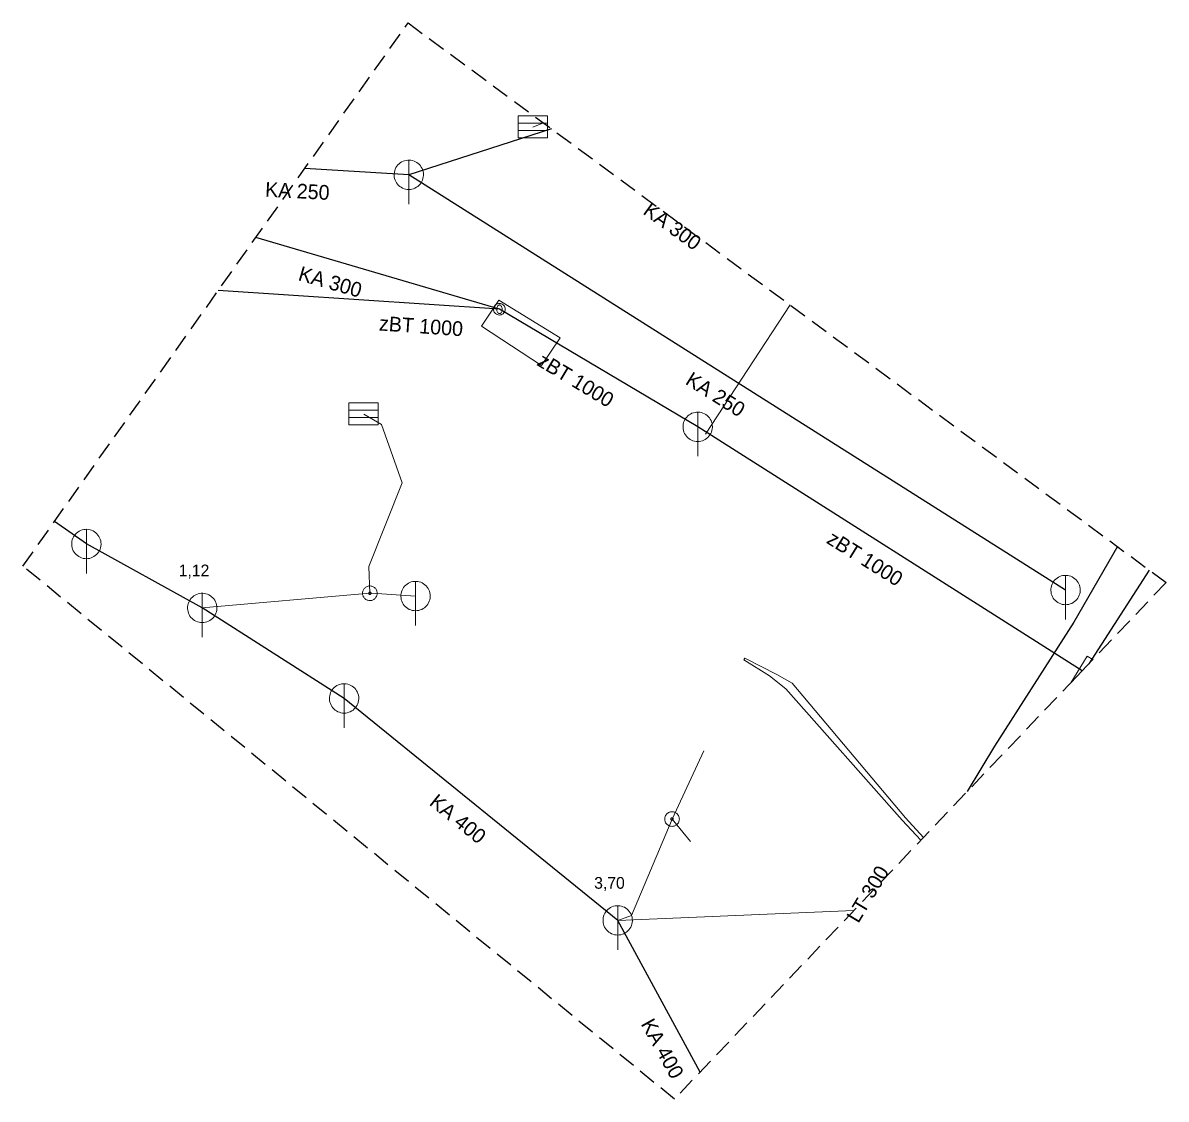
# Model space of a CAD drawing. Extents: x -688182.3 to -688104.4, y -974084.7 to -974011.4.
import ezdxf

# ---------------------------------------------------------------- set-up
doc = ezdxf.new("R2010")
doc.units = 0
doc.header["$LTSCALE"] = 0.4
doc.linetypes.add('MEDIUM_DASHED', pattern=[4.5, 3, -1.5])
for name, color, linetype, lineweight in [('1', 7, 'Continuous', 13), ('11', 7, 'Continuous', 13), ('13', 7, 'Continuous', 13), ('14', 7, 'Continuous', 25), ('17', 7, 'Continuous', 25), ('22', 7, 'Continuous', 13), ('31', 7, 'Continuous', 13)]:
    doc.layers.add(name, color=color, linetype=linetype, lineweight=lineweight)

msp = doc.modelspace()

# ---------------------------------------------------------------- linework, layer by layer
at = {"layer": '1', "linetype": 'MEDIUM_DASHED', "lineweight": 25}
msp.add_lwpolyline([(-688182.317, -974048.412), (-688156.08, -974011.429), (-688104.442, -974049.529), (-688137.937, -974084.698)], close=True, dxfattribs=at)
at = {"layer": '1'}
for points in [[(-688149.886, -974030.3), (-688145.719, -974032.861), (-688146.988, -974034.745), (-688151.07, -974032.079)], [(-688110.944, -974056.356), (-688109.826, -974054.535), (-688109.438, -974054.774)]]:
    msp.add_lwpolyline(points, close=True, dxfattribs=at)
at = {"layer": '11'}
for p, q in [((-688147.579, -974018.52), (-688146.863, -974018.229)), ((-688158.68, -974050.26), (-688170.1, -974051.26)), ((-688135.94, -974060.98), (-688138.1, -974065.629)), ((-688136.85, -974067.16), (-688138.1, -974065.629)), ((-688125.718, -974071.868), (-688141.8, -974072.53))]:
    msp.add_line(p, q, dxfattribs=at)
for points in [[(-688159.1, -974038.059), (-688157.879, -974038.76), (-688156.489, -974042.739), (-688158.76, -974048.43), (-688158.68, -974050.26)], [(-688155.57, -974050.449), (-688157.859, -974050.3), (-688158.68, -974050.26)], [(-688138.1, -974065.629), (-688140.87, -974072.19), (-688141.8, -974072.53)]]:
    msp.add_lwpolyline(points, dxfattribs=at)
at = {"layer": '13'}
msp.add_line((-688130.061, -974030.627), (-688135.823, -974039.428), dxfattribs=at)
for points in [[(-688121.145, -974067.067), (-688122.43, -974065.71), (-688130.35, -974056.76), (-688131.469, -974055.879), (-688133.199, -974054.8)], [(-688133.129, -974054.67), (-688130.949, -974055.78), (-688129.92, -974056.37), (-688122.199, -974065.55), (-688120.971, -974066.884)]]:
    msp.add_lwpolyline(points, dxfattribs=at)
at = {"layer": '14'}
for p, q in [((-688111.294, -974050.04), (-688156.03, -974021.77)), ((-688149.855, -974030.918), (-688169.013, -974029.659)), ((-688110.162, -974055.534), (-688136.35, -974038.93)), ((-688177.993, -974046.906), (-688180.166, -974045.38)), ((-688105.596, -974048.677), (-688109.715, -974055.065))]:
    msp.add_line(p, q, dxfattribs=at)
at = {"layer": '14', "lineweight": 13}
msp.add_line((-688133.199, -974054.8), (-688133.129, -974054.67), dxfattribs=at)
at = {"layer": '14'}
for points in [[(-688146.308, -974018.639), (-688156.03, -974021.77), (-688163.12, -974021.352)], [(-688136.35, -974038.93), (-688149.855, -974030.918), (-688166.443, -974026.036)], [(-688136.185, -974082.859), (-688141.8, -974072.53), (-688160.436, -974057.418), (-688170.1, -974051.26), (-688177.993, -974046.906)]]:
    msp.add_lwpolyline(points, dxfattribs=at)
at = {"layer": '17'}
msp.add_lwpolyline([(-688107.754, -974047.086), (-688110.73, -974052.219), (-688116.14, -974060.66), (-688117.997, -974063.761)], dxfattribs=at)
at = {"layer": '22'}
for p, q in [((-688148.59, -974018.263), (-688146.59, -974018.263)), ((-688148.59, -974018.763), (-688146.59, -974018.763)), ((-688156.03, -974023.77), (-688156.029, -974020.77)), ((-688160.111, -974037.802), (-688158.111, -974037.802)), ((-688160.111, -974038.302), (-688158.111, -974038.302)), ((-688136.35, -974040.93), (-688136.349, -974037.93)), ((-688177.993, -974048.906), (-688177.992, -974045.906)), ((-688155.57, -974052.449), (-688155.569, -974049.449)), ((-688111.294, -974052.04), (-688111.293, -974049.04)), ((-688170.1, -974053.26), (-688170.099, -974050.26)), ((-688160.436, -974059.418), (-688160.435, -974056.418)), ((-688141.8, -974074.53), (-688141.799, -974071.53))]:
    msp.add_line(p, q, dxfattribs=at)
for points in [[(-688148.59, -974017.763), (-688146.59, -974017.763), (-688146.59, -974019.263), (-688148.59, -974019.263)], [(-688155.03, -974021.77), (-688155.035, -974021.661), (-688155.053, -974021.553), (-688155.083, -974021.447), (-688155.123, -974021.346), (-688155.175, -974021.249), (-688155.237, -974021.159), (-688155.309, -974021.076), (-688155.389, -974021.002), (-688155.477, -974020.936), (-688155.571, -974020.881), (-688155.671, -974020.836), (-688155.776, -974020.803), (-688155.883, -974020.781), (-688155.992, -974020.771), (-688156.102, -974020.773), (-688156.21, -974020.787), (-688156.317, -974020.812), (-688156.42, -974020.849), (-688156.518, -974020.898), (-688156.61, -974020.956), (-688156.696, -974021.025), (-688156.773, -974021.102), (-688156.842, -974021.188), (-688156.901, -974021.28), (-688156.949, -974021.378), (-688156.986, -974021.481), (-688157.012, -974021.588), (-688157.026, -974021.696), (-688157.029, -974021.806), (-688157.019, -974021.915), (-688156.998, -974022.022), (-688156.964, -974022.126), (-688156.92, -974022.226), (-688156.865, -974022.321), (-688156.799, -974022.409), (-688156.725, -974022.489), (-688156.642, -974022.561), (-688156.552, -974022.623), (-688156.456, -974022.675), (-688156.354, -974022.716), (-688156.249, -974022.746), (-688156.141, -974022.764), (-688156.031, -974022.77), (-688155.922, -974022.764), (-688155.814, -974022.746), (-688155.709, -974022.717), (-688155.607, -974022.676), (-688155.51, -974022.624), (-688155.42, -974022.562), (-688155.337, -974022.491), (-688155.262, -974022.411), (-688155.197, -974022.323), (-688155.141, -974022.229), (-688155.097, -974022.129), (-688155.063, -974022.025), (-688155.041, -974021.917), (-688155.031, -974021.808)], [(-688149.464, -974030.921), (-688149.47, -974030.853), (-688149.488, -974030.786), (-688149.517, -974030.724), (-688149.557, -974030.667), (-688149.605, -974030.619), (-688149.662, -974030.579), (-688149.723, -974030.55), (-688149.79, -974030.532), (-688149.858, -974030.525), (-688149.928, -974030.531), (-688149.994, -974030.549), (-688150.057, -974030.577), (-688150.113, -974030.617), (-688150.162, -974030.665), (-688150.201, -974030.721), (-688150.232, -974030.783), (-688150.25, -974030.85), (-688150.257, -974030.918), (-688150.25, -974030.987), (-688150.233, -974031.054), (-688150.205, -974031.116), (-688150.166, -974031.173), (-688150.118, -974031.222), (-688150.062, -974031.262), (-688150, -974031.292), (-688149.934, -974031.311), (-688149.865, -974031.318), (-688149.796, -974031.312), (-688149.73, -974031.295), (-688149.667, -974031.267), (-688149.61, -974031.228), (-688149.561, -974031.18), (-688149.52, -974031.124), (-688149.49, -974031.062), (-688149.472, -974030.996), (-688149.464, -974030.928)], [(-688149.85, -974031.223), (-688149.813, -974031.216), (-688149.777, -974031.198), (-688149.745, -974031.169), (-688149.718, -974031.13), (-688149.696, -974031.083), (-688149.679, -974031.03), (-688149.671, -974030.973), (-688149.669, -974030.913), (-688149.676, -974030.854), (-688149.689, -974030.799), (-688149.708, -974030.748), (-688149.733, -974030.705), (-688149.764, -974030.671), (-688149.798, -974030.647), (-688149.834, -974030.635), (-688149.87, -974030.634), (-688149.907, -974030.646), (-688149.941, -974030.668), (-688149.972, -974030.702), (-688149.997, -974030.744), (-688150.017, -974030.795), (-688150.03, -974030.85), (-688150.035, -974030.909), (-688150.034, -974030.968), (-688150.025, -974031.026), (-688150.009, -974031.079), (-688149.986, -974031.127), (-688149.959, -974031.167), (-688149.927, -974031.196), (-688149.892, -974031.215), (-688149.855, -974031.223)], [(-688160.111, -974037.302), (-688158.111, -974037.302), (-688158.111, -974038.802), (-688160.111, -974038.802)], [(-688135.35, -974038.93), (-688135.355, -974038.821), (-688135.373, -974038.713), (-688135.403, -974038.607), (-688135.443, -974038.506), (-688135.495, -974038.409), (-688135.557, -974038.319), (-688135.629, -974038.236), (-688135.709, -974038.162), (-688135.797, -974038.096), (-688135.891, -974038.041), (-688135.991, -974037.996), (-688136.096, -974037.963), (-688136.203, -974037.941), (-688136.312, -974037.931), (-688136.422, -974037.933), (-688136.53, -974037.947), (-688136.637, -974037.972), (-688136.74, -974038.009), (-688136.838, -974038.058), (-688136.93, -974038.116), (-688137.016, -974038.185), (-688137.093, -974038.262), (-688137.162, -974038.348), (-688137.221, -974038.44), (-688137.269, -974038.538), (-688137.306, -974038.641), (-688137.332, -974038.748), (-688137.346, -974038.856), (-688137.349, -974038.966), (-688137.339, -974039.075), (-688137.318, -974039.182), (-688137.284, -974039.286), (-688137.24, -974039.386), (-688137.185, -974039.481), (-688137.119, -974039.569), (-688137.045, -974039.649), (-688136.962, -974039.721), (-688136.872, -974039.783), (-688136.776, -974039.835), (-688136.674, -974039.876), (-688136.569, -974039.906), (-688136.461, -974039.924), (-688136.351, -974039.93), (-688136.242, -974039.924), (-688136.134, -974039.906), (-688136.029, -974039.877), (-688135.927, -974039.836), (-688135.83, -974039.784), (-688135.74, -974039.722), (-688135.657, -974039.651), (-688135.582, -974039.571), (-688135.517, -974039.483), (-688135.461, -974039.389), (-688135.417, -974039.289), (-688135.383, -974039.185), (-688135.361, -974039.077), (-688135.351, -974038.968)], [(-688176.993, -974046.906), (-688176.998, -974046.797), (-688177.016, -974046.689), (-688177.046, -974046.583), (-688177.086, -974046.482), (-688177.138, -974046.385), (-688177.2, -974046.295), (-688177.272, -974046.212), (-688177.352, -974046.138), (-688177.44, -974046.072), (-688177.534, -974046.017), (-688177.634, -974045.972), (-688177.739, -974045.939), (-688177.846, -974045.917), (-688177.955, -974045.907), (-688178.065, -974045.909), (-688178.173, -974045.923), (-688178.28, -974045.948), (-688178.383, -974045.985), (-688178.481, -974046.034), (-688178.573, -974046.092), (-688178.659, -974046.161), (-688178.736, -974046.238), (-688178.805, -974046.324), (-688178.864, -974046.416), (-688178.912, -974046.514), (-688178.949, -974046.617), (-688178.975, -974046.724), (-688178.989, -974046.832), (-688178.992, -974046.942), (-688178.982, -974047.051), (-688178.961, -974047.158), (-688178.927, -974047.262), (-688178.883, -974047.362), (-688178.828, -974047.457), (-688178.762, -974047.545), (-688178.688, -974047.625), (-688178.605, -974047.697), (-688178.515, -974047.759), (-688178.419, -974047.811), (-688178.317, -974047.852), (-688178.212, -974047.882), (-688178.104, -974047.9), (-688177.994, -974047.906), (-688177.885, -974047.9), (-688177.777, -974047.882), (-688177.672, -974047.853), (-688177.57, -974047.812), (-688177.473, -974047.76), (-688177.383, -974047.698), (-688177.3, -974047.627), (-688177.225, -974047.547), (-688177.16, -974047.459), (-688177.104, -974047.365), (-688177.06, -974047.265), (-688177.026, -974047.161), (-688177.004, -974047.053), (-688176.994, -974046.944)], [(-688154.57, -974050.449), (-688154.575, -974050.34), (-688154.593, -974050.232), (-688154.623, -974050.126), (-688154.663, -974050.025), (-688154.715, -974049.928), (-688154.777, -974049.838), (-688154.849, -974049.755), (-688154.929, -974049.681), (-688155.017, -974049.615), (-688155.111, -974049.56), (-688155.211, -974049.515), (-688155.316, -974049.482), (-688155.423, -974049.46), (-688155.532, -974049.45), (-688155.642, -974049.452), (-688155.75, -974049.466), (-688155.857, -974049.491), (-688155.96, -974049.528), (-688156.058, -974049.577), (-688156.15, -974049.635), (-688156.236, -974049.704), (-688156.313, -974049.781), (-688156.382, -974049.867), (-688156.441, -974049.959), (-688156.489, -974050.057), (-688156.526, -974050.16), (-688156.552, -974050.267), (-688156.566, -974050.375), (-688156.569, -974050.485), (-688156.559, -974050.594), (-688156.538, -974050.701), (-688156.504, -974050.805), (-688156.46, -974050.905), (-688156.405, -974051), (-688156.339, -974051.088), (-688156.265, -974051.168), (-688156.182, -974051.24), (-688156.092, -974051.302), (-688155.996, -974051.354), (-688155.894, -974051.395), (-688155.789, -974051.425), (-688155.681, -974051.443), (-688155.571, -974051.449), (-688155.462, -974051.443), (-688155.354, -974051.425), (-688155.249, -974051.396), (-688155.147, -974051.355), (-688155.05, -974051.303), (-688154.96, -974051.241), (-688154.877, -974051.17), (-688154.802, -974051.09), (-688154.737, -974051.002), (-688154.681, -974050.908), (-688154.637, -974050.808), (-688154.603, -974050.704), (-688154.581, -974050.596), (-688154.571, -974050.487)], [(-688110.294, -974050.04), (-688110.299, -974049.931), (-688110.317, -974049.823), (-688110.347, -974049.717), (-688110.387, -974049.616), (-688110.439, -974049.519), (-688110.501, -974049.429), (-688110.573, -974049.346), (-688110.653, -974049.272), (-688110.741, -974049.206), (-688110.835, -974049.151), (-688110.935, -974049.106), (-688111.04, -974049.073), (-688111.147, -974049.051), (-688111.256, -974049.041), (-688111.366, -974049.043), (-688111.474, -974049.057), (-688111.581, -974049.082), (-688111.684, -974049.119), (-688111.782, -974049.168), (-688111.874, -974049.226), (-688111.96, -974049.295), (-688112.037, -974049.372), (-688112.106, -974049.458), (-688112.165, -974049.55), (-688112.213, -974049.648), (-688112.25, -974049.751), (-688112.276, -974049.858), (-688112.29, -974049.966), (-688112.293, -974050.076), (-688112.283, -974050.185), (-688112.262, -974050.292), (-688112.228, -974050.396), (-688112.184, -974050.496), (-688112.129, -974050.591), (-688112.063, -974050.679), (-688111.989, -974050.759), (-688111.906, -974050.831), (-688111.816, -974050.893), (-688111.72, -974050.945), (-688111.618, -974050.986), (-688111.513, -974051.016), (-688111.405, -974051.034), (-688111.295, -974051.04), (-688111.186, -974051.034), (-688111.078, -974051.016), (-688110.973, -974050.987), (-688110.871, -974050.946), (-688110.774, -974050.894), (-688110.684, -974050.832), (-688110.601, -974050.761), (-688110.526, -974050.681), (-688110.461, -974050.593), (-688110.405, -974050.499), (-688110.361, -974050.399), (-688110.327, -974050.295), (-688110.305, -974050.187), (-688110.295, -974050.078)], [(-688169.1, -974051.26), (-688169.105, -974051.151), (-688169.123, -974051.043), (-688169.153, -974050.937), (-688169.193, -974050.836), (-688169.245, -974050.739), (-688169.307, -974050.649), (-688169.379, -974050.566), (-688169.459, -974050.492), (-688169.547, -974050.426), (-688169.641, -974050.371), (-688169.741, -974050.326), (-688169.846, -974050.293), (-688169.953, -974050.271), (-688170.062, -974050.261), (-688170.172, -974050.263), (-688170.28, -974050.277), (-688170.387, -974050.302), (-688170.49, -974050.339), (-688170.588, -974050.388), (-688170.68, -974050.446), (-688170.766, -974050.515), (-688170.843, -974050.592), (-688170.912, -974050.678), (-688170.971, -974050.77), (-688171.019, -974050.868), (-688171.056, -974050.971), (-688171.082, -974051.078), (-688171.096, -974051.186), (-688171.099, -974051.296), (-688171.089, -974051.405), (-688171.068, -974051.512), (-688171.034, -974051.616), (-688170.99, -974051.716), (-688170.935, -974051.811), (-688170.869, -974051.899), (-688170.795, -974051.979), (-688170.712, -974052.051), (-688170.622, -974052.113), (-688170.526, -974052.165), (-688170.424, -974052.206), (-688170.319, -974052.236), (-688170.211, -974052.254), (-688170.101, -974052.26), (-688169.992, -974052.254), (-688169.884, -974052.236), (-688169.779, -974052.207), (-688169.677, -974052.166), (-688169.58, -974052.114), (-688169.49, -974052.052), (-688169.407, -974051.981), (-688169.332, -974051.901), (-688169.267, -974051.813), (-688169.211, -974051.719), (-688169.167, -974051.619), (-688169.133, -974051.515), (-688169.111, -974051.407), (-688169.101, -974051.298)], [(-688159.436, -974057.418), (-688159.441, -974057.309), (-688159.459, -974057.201), (-688159.489, -974057.095), (-688159.529, -974056.994), (-688159.581, -974056.897), (-688159.643, -974056.807), (-688159.715, -974056.724), (-688159.795, -974056.65), (-688159.883, -974056.584), (-688159.977, -974056.529), (-688160.077, -974056.484), (-688160.182, -974056.451), (-688160.289, -974056.429), (-688160.398, -974056.419), (-688160.508, -974056.421), (-688160.616, -974056.435), (-688160.723, -974056.46), (-688160.826, -974056.497), (-688160.924, -974056.546), (-688161.016, -974056.604), (-688161.102, -974056.673), (-688161.179, -974056.75), (-688161.248, -974056.836), (-688161.307, -974056.928), (-688161.355, -974057.026), (-688161.392, -974057.129), (-688161.418, -974057.236), (-688161.432, -974057.344), (-688161.435, -974057.454), (-688161.425, -974057.563), (-688161.404, -974057.67), (-688161.37, -974057.774), (-688161.326, -974057.874), (-688161.271, -974057.969), (-688161.205, -974058.057), (-688161.131, -974058.137), (-688161.048, -974058.209), (-688160.958, -974058.271), (-688160.862, -974058.323), (-688160.76, -974058.364), (-688160.655, -974058.394), (-688160.547, -974058.412), (-688160.437, -974058.418), (-688160.328, -974058.412), (-688160.22, -974058.394), (-688160.115, -974058.365), (-688160.013, -974058.324), (-688159.916, -974058.272), (-688159.826, -974058.21), (-688159.743, -974058.139), (-688159.668, -974058.059), (-688159.603, -974057.971), (-688159.547, -974057.877), (-688159.503, -974057.777), (-688159.469, -974057.673), (-688159.447, -974057.565), (-688159.437, -974057.456)], [(-688140.8, -974072.53), (-688140.805, -974072.421), (-688140.823, -974072.313), (-688140.853, -974072.207), (-688140.893, -974072.106), (-688140.945, -974072.009), (-688141.007, -974071.919), (-688141.079, -974071.836), (-688141.159, -974071.762), (-688141.247, -974071.696), (-688141.341, -974071.641), (-688141.441, -974071.596), (-688141.546, -974071.563), (-688141.653, -974071.541), (-688141.762, -974071.531), (-688141.872, -974071.533), (-688141.98, -974071.547), (-688142.087, -974071.572), (-688142.19, -974071.609), (-688142.288, -974071.658), (-688142.38, -974071.716), (-688142.466, -974071.785), (-688142.543, -974071.862), (-688142.612, -974071.948), (-688142.671, -974072.04), (-688142.719, -974072.138), (-688142.756, -974072.241), (-688142.782, -974072.348), (-688142.796, -974072.456), (-688142.799, -974072.566), (-688142.789, -974072.675), (-688142.768, -974072.782), (-688142.734, -974072.886), (-688142.69, -974072.986), (-688142.635, -974073.081), (-688142.569, -974073.169), (-688142.495, -974073.249), (-688142.412, -974073.321), (-688142.322, -974073.383), (-688142.226, -974073.435), (-688142.124, -974073.476), (-688142.019, -974073.506), (-688141.911, -974073.524), (-688141.801, -974073.53), (-688141.692, -974073.524), (-688141.584, -974073.506), (-688141.479, -974073.477), (-688141.377, -974073.436), (-688141.28, -974073.384), (-688141.19, -974073.322), (-688141.107, -974073.251), (-688141.032, -974073.171), (-688140.967, -974073.083), (-688140.911, -974072.989), (-688140.867, -974072.889), (-688140.833, -974072.785), (-688140.811, -974072.677), (-688140.801, -974072.568)]]:
    msp.add_lwpolyline(points, close=True, dxfattribs=at)
at = {"layer": '31'}
for points in [[(-688158.658, -974050.759), (-688158.606, -974050.754), (-688158.554, -974050.743), (-688158.505, -974050.727), (-688158.457, -974050.707), (-688158.411, -974050.681), (-688158.368, -974050.65), (-688158.33, -974050.616), (-688158.294, -974050.577), (-688158.263, -974050.536), (-688158.236, -974050.49), (-688158.214, -974050.442), (-688158.198, -974050.393), (-688158.186, -974050.342), (-688158.181, -974050.29), (-688158.18, -974050.238), (-688158.185, -974050.186), (-688158.196, -974050.134), (-688158.212, -974050.084), (-688158.232, -974050.037), (-688158.258, -974049.991), (-688158.289, -974049.948), (-688158.323, -974049.909), (-688158.362, -974049.873), (-688158.403, -974049.842), (-688158.449, -974049.816), (-688158.497, -974049.794), (-688158.546, -974049.777), (-688158.597, -974049.766), (-688158.649, -974049.761), (-688158.701, -974049.76), (-688158.753, -974049.765), (-688158.805, -974049.776), (-688158.855, -974049.791), (-688158.902, -974049.812), (-688158.948, -974049.838), (-688158.991, -974049.868), (-688159.03, -974049.902), (-688159.066, -974049.941), (-688159.097, -974049.983), (-688159.123, -974050.029), (-688159.145, -974050.077), (-688159.162, -974050.125), (-688159.173, -974050.177), (-688159.178, -974050.229), (-688159.179, -974050.281), (-688159.174, -974050.333), (-688159.163, -974050.385), (-688159.148, -974050.434), (-688159.127, -974050.482), (-688159.101, -974050.528), (-688159.071, -974050.571), (-688159.037, -974050.609), (-688158.998, -974050.645), (-688158.956, -974050.676), (-688158.91, -974050.703), (-688158.862, -974050.725), (-688158.814, -974050.741), (-688158.762, -974050.753), (-688158.71, -974050.758)], [(-688158.676, -974050.341), (-688158.667, -974050.341), (-688158.659, -974050.339), (-688158.651, -974050.336), (-688158.643, -974050.333), (-688158.635, -974050.329), (-688158.629, -974050.323), (-688158.622, -974050.318), (-688158.616, -974050.312), (-688158.611, -974050.305), (-688158.607, -974050.297), (-688158.603, -974050.289), (-688158.6, -974050.281), (-688158.599, -974050.273), (-688158.597, -974050.265), (-688158.598, -974050.256), (-688158.598, -974050.247), (-688158.6, -974050.239), (-688158.603, -974050.231), (-688158.606, -974050.223), (-688158.61, -974050.215), (-688158.616, -974050.209), (-688158.621, -974050.202), (-688158.627, -974050.196), (-688158.634, -974050.19), (-688158.642, -974050.187), (-688158.65, -974050.183), (-688158.658, -974050.18), (-688158.666, -974050.179), (-688158.674, -974050.177), (-688158.683, -974050.178), (-688158.692, -974050.178), (-688158.7, -974050.18), (-688158.708, -974050.183), (-688158.716, -974050.186), (-688158.724, -974050.19), (-688158.73, -974050.195), (-688158.737, -974050.201), (-688158.743, -974050.207), (-688158.749, -974050.214), (-688158.752, -974050.222), (-688158.756, -974050.23), (-688158.759, -974050.238), (-688158.76, -974050.246), (-688158.762, -974050.254), (-688158.761, -974050.263), (-688158.761, -974050.272), (-688158.759, -974050.28), (-688158.756, -974050.288), (-688158.753, -974050.296), (-688158.749, -974050.304), (-688158.744, -974050.31), (-688158.738, -974050.317), (-688158.732, -974050.323), (-688158.725, -974050.328), (-688158.717, -974050.332), (-688158.709, -974050.336), (-688158.701, -974050.339), (-688158.693, -974050.34), (-688158.685, -974050.342)], [(-688137.6, -974065.629), (-688137.603, -974065.576), (-688137.611, -974065.524), (-688137.625, -974065.475), (-688137.642, -974065.426), (-688137.667, -974065.379), (-688137.696, -974065.335), (-688137.728, -974065.294), (-688137.766, -974065.257), (-688137.806, -974065.225), (-688137.85, -974065.196), (-688137.897, -974065.171), (-688137.946, -974065.154), (-688137.995, -974065.14), (-688138.048, -974065.132), (-688138.1, -974065.129), (-688138.152, -974065.132), (-688138.204, -974065.14), (-688138.255, -974065.154), (-688138.303, -974065.171), (-688138.35, -974065.196), (-688138.394, -974065.225), (-688138.434, -974065.257), (-688138.472, -974065.294), (-688138.505, -974065.335), (-688138.532, -974065.379), (-688138.557, -974065.426), (-688138.576, -974065.475), (-688138.588, -974065.524), (-688138.597, -974065.576), (-688138.6, -974065.629), (-688138.597, -974065.681), (-688138.588, -974065.733), (-688138.576, -974065.784), (-688138.557, -974065.831), (-688138.532, -974065.879), (-688138.505, -974065.923), (-688138.472, -974065.963), (-688138.434, -974066), (-688138.394, -974066.034), (-688138.35, -974066.061), (-688138.303, -974066.086), (-688138.255, -974066.105), (-688138.204, -974066.117), (-688138.152, -974066.125), (-688138.1, -974066.129), (-688138.048, -974066.125), (-688137.995, -974066.117), (-688137.946, -974066.105), (-688137.897, -974066.086), (-688137.85, -974066.061), (-688137.806, -974066.034), (-688137.766, -974066), (-688137.728, -974065.963), (-688137.696, -974065.923), (-688137.667, -974065.879), (-688137.642, -974065.831), (-688137.625, -974065.784), (-688137.611, -974065.733), (-688137.603, -974065.681)], [(-688138.017, -974065.629), (-688138.017, -974065.62), (-688138.02, -974065.612), (-688138.022, -974065.603), (-688138.025, -974065.595), (-688138.029, -974065.588), (-688138.034, -974065.581), (-688138.039, -974065.573), (-688138.044, -974065.568), (-688138.052, -974065.563), (-688138.059, -974065.558), (-688138.066, -974065.554), (-688138.075, -974065.551), (-688138.083, -974065.549), (-688138.091, -974065.546), (-688138.1, -974065.546), (-688138.108, -974065.546), (-688138.117, -974065.549), (-688138.125, -974065.551), (-688138.133, -974065.554), (-688138.141, -974065.558), (-688138.147, -974065.563), (-688138.155, -974065.568), (-688138.161, -974065.573), (-688138.167, -974065.581), (-688138.171, -974065.588), (-688138.174, -974065.595), (-688138.178, -974065.603), (-688138.179, -974065.612), (-688138.182, -974065.62), (-688138.182, -974065.629), (-688138.182, -974065.637), (-688138.179, -974065.646), (-688138.178, -974065.654), (-688138.174, -974065.662), (-688138.171, -974065.669), (-688138.167, -974065.676), (-688138.161, -974065.684), (-688138.155, -974065.69), (-688138.147, -974065.696), (-688138.141, -974065.7), (-688138.133, -974065.703), (-688138.125, -974065.706), (-688138.117, -974065.708), (-688138.108, -974065.711), (-688138.1, -974065.711), (-688138.091, -974065.711), (-688138.083, -974065.708), (-688138.075, -974065.706), (-688138.066, -974065.703), (-688138.059, -974065.7), (-688138.052, -974065.696), (-688138.044, -974065.69), (-688138.039, -974065.684), (-688138.034, -974065.676), (-688138.029, -974065.669), (-688138.025, -974065.662), (-688138.022, -974065.654), (-688138.02, -974065.646), (-688138.017, -974065.637)]]:
    msp.add_lwpolyline(points, close=True, dxfattribs=at)

# ---------------------------------------------------------------- texts
at = {"layer": '1'}
for s, rotation, p in [('KA 250', 357, (-688165.834, -974023.255)), ('KA 300', 324, (-688140.141, -974024.391)), ('KA 300', 344, (-688163.621, -974028.935)), ('zBT 1000', 356, (-688158.083, -974032.366)), ('zBT 1000', 329, (-688147.368, -974034.701)), ('KA 250', 328, (-688137.258, -974035.98)), ('zBT 1000', 328, (-688127.645, -974046.799)), ('KA 400', 321, (-688154.698, -974064.625)), ('LT 300', 59, (-688125.412, -974072.776)), ('KA 400', 299, (-688140.25, -974079.582))]:
    msp.add_text(s, height=1, rotation=rotation, dxfattribs=at).set_placement(p)
for s, p in [('1,12', (-688171.699, -974049.107)), ('3,70', (-688143.4, -974070.377))]:
    msp.add_text(s, height=0.8, dxfattribs=at).set_placement(p)

doc.saveas('drawing.dxf')
